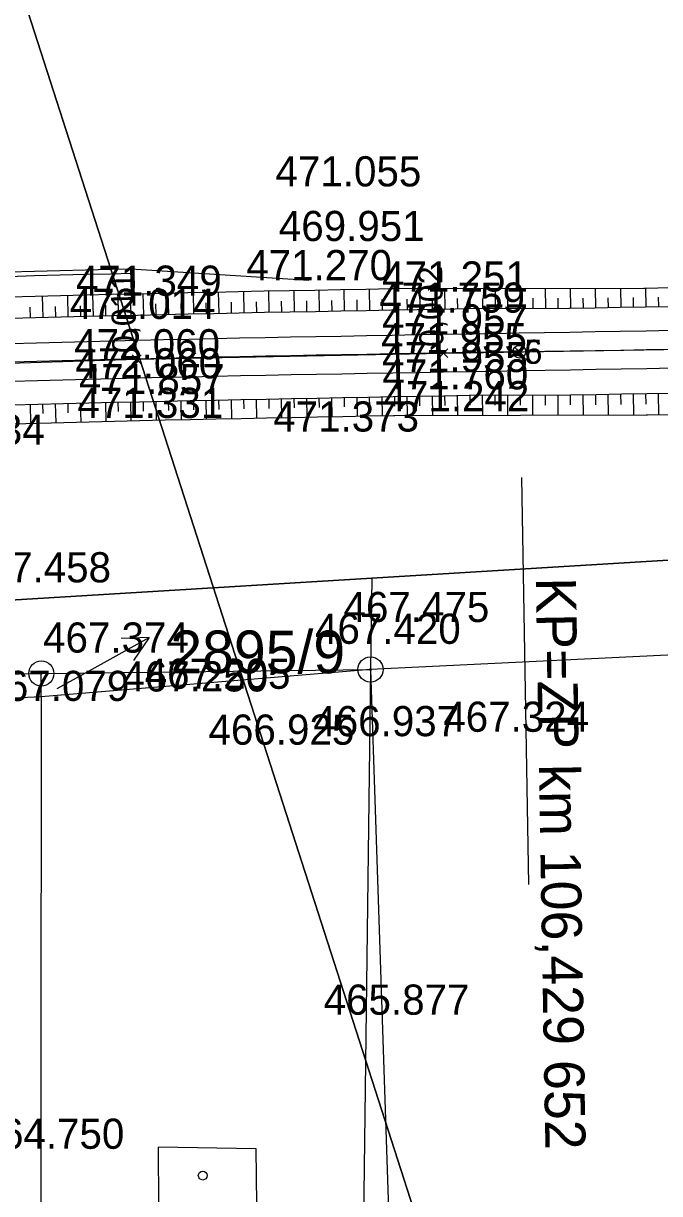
# Model space of a CAD drawing. Extents: x -758836 to -757729, y -1175316 to -1174366.
# Drawn here: x -758198.73 to -758173.42, y -1174797.31 to -1174750.75 of the extents above; entities that cross this region are included whole.
import ezdxf

# ---------------------------------------------------------------- set-up
doc = ezdxf.new("R2010")
doc.units = 0
for name, color, linetype in [('_NOR-body-stávající osa', 7, 'Continuous'), ('_NOR-návrh tenká', 7, 'Continuous'), ('_NOR-osa', 7, 'Continuous'), ('_NOR-pomocná', 7, 'Continuous'), ('_NOR-popis', 7, 'Continuous'), ('_NOR-posuny', 7, 'Continuous'), ('_NOR-svahy', 7, 'Continuous'), ('_NOR-vytyčení', 7, 'Continuous'), ('_vytyčený bod', 7, 'Continuous'), ('G_Obvod stavby', 7, 'Continuous'), ('Hranice parcel', 7, 'Continuous'), ('Parcelní čísla', 7, 'Continuous'), ('Pop  PČ popisy', 7, 'Continuous'), ('Vrstva 1', 7, 'Continuous'), ('Vrstva 61', 7, 'Continuous'), ('Značky bodu BP', 7, 'Continuous'), ('Značky budov', 7, 'Continuous')]:
    doc.layers.add(name, color=color, linetype=linetype)

# ---------------------------------------------------------------- blocks, each defined once
blk = doc.blocks.new('POINT_DISPLAY')
for p, q in [((-0.175, -0.175), (0.175, 0.175)), ((-0.175, 0.175), (0.175, -0.175))]:
    blk.add_line(p, q)

msp = doc.modelspace()

# ---------------------------------------------------------------- linework, layer by layer
at = {"layer": '_NOR-návrh tenká'}
for p, q in [((-758194.43, -1174761.512), (-758194.453, -1174760.512)), ((-758194.453, -1174760.512), (-758187.38, -1174760.969))]:
    msp.add_line(p, q, dxfattribs=at)
for points in [[(-758206.238, -1174760.86), (-758205.398, -1174760.83), (-758204.383, -1174760.794), (-758203.368, -1174760.76), (-758202.353, -1174760.727), (-758201.338, -1174760.696), (-758200.324, -1174760.665), (-758199.309, -1174760.636), (-758198.295, -1174760.608), (-758197.281, -1174760.581), (-758196.267, -1174760.556), (-758195.253, -1174760.531), (-758194.453, -1174760.512)], [(-758206.233, -1174761.04), (-758205.392, -1174761.009), (-758204.377, -1174760.974), (-758203.362, -1174760.94), (-758202.347, -1174760.907), (-758201.333, -1174760.875), (-758200.318, -1174760.845), (-758199.304, -1174760.816), (-758198.29, -1174760.788), (-758197.276, -1174760.761), (-758196.262, -1174760.736), (-758195.249, -1174760.711), (-758194.449, -1174760.692)], [(-758199.281, -1174761.636), (-758198.268, -1174761.608), (-758197.255, -1174761.581), (-758196.242, -1174761.555), (-758195.229, -1174761.53), (-758194.216, -1174761.507), (-758193.204, -1174761.483), (-758192.191, -1174761.461), (-758191.179, -1174761.44), (-758190.167, -1174761.419), (-758189.154, -1174761.398), (-758188.143, -1174761.379), (-758187.131, -1174761.36), (-758186.119, -1174761.341), (-758185.108, -1174761.322), (-758184.096, -1174761.304), (-758184.038, -1174761.303), (-758174.039, -1174761.282), (-758173.987, -1174761.281), (-758172.977, -1174761.263)], [(-758199.257, -1174762.485), (-758198.245, -1174762.458), (-758197.233, -1174762.431), (-758196.221, -1174762.405), (-758195.208, -1174762.38), (-758194.196, -1174762.356), (-758193.185, -1174762.333), (-758192.173, -1174762.311), (-758191.161, -1174762.289), (-758190.149, -1174762.269), (-758189.138, -1174762.248), (-758188.126, -1174762.229), (-758187.115, -1174762.209), (-758186.103, -1174762.191), (-758185.092, -1174762.172), (-758184.081, -1174762.154), (-758183.07, -1174762.137), (-758182.059, -1174762.119), (-758181.048, -1174762.102), (-758181.026, -1174762.101), (-758177.026, -1174762.084), (-758177.005, -1174762.083), (-758175.995, -1174762.066), (-758174.984, -1174762.048), (-758173.974, -1174762.031), (-758172.964, -1174762.013)], [(-758199.229, -1174763.485), (-758198.218, -1174763.457), (-758197.207, -1174763.43), (-758196.196, -1174763.405), (-758195.184, -1174763.38), (-758194.173, -1174763.356), (-758193.162, -1174763.333), (-758192.151, -1174763.311), (-758191.14, -1174763.289), (-758190.129, -1174763.268), (-758189.118, -1174763.248), (-758188.107, -1174763.228), (-758187.096, -1174763.209), (-758186.085, -1174763.191), (-758185.074, -1174763.172), (-758184.063, -1174763.154), (-758183.053, -1174763.137), (-758182.042, -1174763.119), (-758181.031, -1174763.102), (-758180.021, -1174763.085), (-758179.01, -1174763.067), (-758177.999, -1174763.05), (-758176.989, -1174763.033), (-758175.978, -1174763.016), (-758174.968, -1174762.998), (-758173.957, -1174762.981), (-758172.947, -1174762.963)], [(-758199.187, -1174764.985), (-758198.177, -1174764.957), (-758197.168, -1174764.93), (-758196.158, -1174764.904), (-758195.148, -1174764.879), (-758194.138, -1174764.856), (-758193.129, -1174764.833), (-758192.119, -1174764.81), (-758191.109, -1174764.789), (-758190.098, -1174764.768), (-758189.088, -1174764.748), (-758188.078, -1174764.728), (-758187.068, -1174764.709), (-758186.058, -1174764.69), (-758185.047, -1174764.672), (-758184.037, -1174764.654), (-758183.027, -1174764.636), (-758182.016, -1174764.619), (-758181.006, -1174764.602), (-758179.995, -1174764.584), (-758178.984, -1174764.567), (-758177.974, -1174764.55), (-758176.963, -1174764.533), (-758175.952, -1174764.516), (-758174.942, -1174764.498), (-758173.931, -1174764.48), (-758172.92, -1174764.462)], [(-758199.16, -1174765.934), (-758198.152, -1174765.906), (-758197.143, -1174765.88), (-758196.134, -1174765.854), (-758195.125, -1174765.829), (-758194.116, -1174765.805), (-758193.107, -1174765.782), (-758192.098, -1174765.76), (-758191.089, -1174765.739), (-758190.079, -1174765.718), (-758189.07, -1174765.698), (-758188.06, -1174765.678), (-758187.05, -1174765.659), (-758186.04, -1174765.64), (-758185.03, -1174765.622), (-758184.02, -1174765.604), (-758183.01, -1174765.586), (-758182, -1174765.569), (-758180.989, -1174765.551), (-758180.968, -1174765.551), (-758176.968, -1174765.533), (-758176.946, -1174765.533), (-758175.935, -1174765.515), (-758174.924, -1174765.498), (-758173.913, -1174765.48), (-758172.902, -1174765.462)], [(-758199.139, -1174766.684), (-758198.131, -1174766.656), (-758197.124, -1174766.629), (-758196.116, -1174766.604), (-758195.107, -1174766.579), (-758194.099, -1174766.555), (-758193.09, -1174766.532), (-758192.082, -1174766.51), (-758191.073, -1174766.488), (-758190.064, -1174766.468), (-758189.055, -1174766.447), (-758188.046, -1174766.428), (-758187.036, -1174766.409), (-758186.027, -1174766.39), (-758185.017, -1174766.372), (-758184.007, -1174766.354), (-758183.955, -1174766.353), (-758173.956, -1174766.331), (-758173.898, -1174766.33), (-758172.887, -1174766.312)]]:
    msp.add_lwpolyline(points, dxfattribs=at)
at = {"layer": '_NOR-osa'}
for points in [[(-758178.997, -1174763.817), (-758180.008, -1174763.834), (-758181.018, -1174763.852), (-758182.029, -1174763.869), (-758183.04, -1174763.886), (-758184.05, -1174763.904), (-758185.061, -1174763.922), (-758186.071, -1174763.94), (-758187.082, -1174763.959), (-758188.093, -1174763.978), (-758189.103, -1174763.998), (-758190.114, -1174764.018), (-758191.124, -1174764.039), (-758192.135, -1174764.061), (-758193.145, -1174764.083), (-758194.156, -1174764.106), (-758195.166, -1174764.13), (-758196.177, -1174764.154), (-758197.187, -1174764.18), (-758198.198, -1174764.207), (-758199.208, -1174764.235)], [(-758178.997, -1174763.817), (-758177.987, -1174763.8), (-758176.976, -1174763.783), (-758175.965, -1174763.766), (-758174.955, -1174763.748), (-758173.944, -1174763.73), (-758172.933, -1174763.712)]]:
    msp.add_lwpolyline(points, dxfattribs=at)
msp.add_circle((-758178.997, -1174763.817), 0.25, dxfattribs=at)
msp.add_circle((-758178.997, -1174763.817), 0.25, dxfattribs=at)
at = {"layer": '_NOR-pomocná'}
for points in [[(-758217.708, -1174690.839), (-758117.765, -1174658.647), (-758072.236, -1174799.995), (-758172.179, -1174832.187)], [(-758317.652, -1174723.031), (-758217.708, -1174690.839), (-758172.179, -1174832.187), (-758272.123, -1174864.38)]]:
    msp.add_lwpolyline(points, close=True, dxfattribs=at)
at = {"layer": '_NOR-popis'}
msp.add_line((-758178.912, -1174768.817), (-758178.638, -1174785.011), dxfattribs=at)
msp.add_line((-758178.912, -1174768.817), (-758178.638, -1174785.011), dxfattribs=at)
at = {"layer": '_NOR-svahy'}
for points in [[(-758197.946, -1174762.45), (-758197.969, -1174761.6)], [(-758196.946, -1174762.424), (-758196.968, -1174761.574)], [(-758195.947, -1174762.398), (-758195.968, -1174761.549)], [(-758194.947, -1174762.374), (-758194.967, -1174761.524)], [(-758193.947, -1174762.351), (-758193.967, -1174761.501)], [(-758192.948, -1174762.328), (-758192.966, -1174761.478)], [(-758191.948, -1174762.306), (-758191.966, -1174761.456)], [(-758190.948, -1174762.285), (-758190.966, -1174761.435)], [(-758189.948, -1174762.264), (-758189.965, -1174761.415)], [(-758188.948, -1174762.245), (-758188.965, -1174761.395)], [(-758187.949, -1174762.225), (-758187.965, -1174761.375)], [(-758186.949, -1174762.206), (-758186.965, -1174761.356)], [(-758185.949, -1174762.188), (-758185.964, -1174761.338)], [(-758184.949, -1174762.17), (-758184.964, -1174761.32)], [(-758183.949, -1174762.152), (-758183.964, -1174761.303)], [(-758182.949, -1174762.135), (-758182.964, -1174761.301)], [(-758181.95, -1174762.117), (-758181.964, -1174761.299)], [(-758181.45, -1174762.109), (-758181.457, -1174761.703)], [(-758180.95, -1174762.101), (-758180.953, -1174761.297)], [(-758180.45, -1174762.099), (-758180.452, -1174761.697)], [(-758179.95, -1174762.097), (-758179.953, -1174761.295)], [(-758179.45, -1174762.094), (-758179.452, -1174761.694)], [(-758178.95, -1174762.092), (-758178.953, -1174761.292)], [(-758178.45, -1174762.09), (-758178.452, -1174761.691)], [(-758177.95, -1174762.088), (-758177.953, -1174761.29)], [(-758177.45, -1174762.085), (-758177.452, -1174761.687)], [(-758176.95, -1174762.082), (-758176.963, -1174761.288)], [(-758176.45, -1174762.074), (-758176.457, -1174761.68)], [(-758175.95, -1174762.065), (-758175.963, -1174761.286)], [(-758175.45, -1174762.056), (-758175.457, -1174761.671)], [(-758174.95, -1174762.048), (-758174.963, -1174761.284)], [(-758174.45, -1174762.039), (-758174.457, -1174761.661)], [(-758173.95, -1174762.03), (-758173.964, -1174761.28)], [(-758173.45, -1174762.021), (-758173.457, -1174761.646)], [(-758198.446, -1174762.463), (-758198.458, -1174762.038)], [(-758197.446, -1174762.436), (-758197.457, -1174762.012)], [(-758196.447, -1174762.411), (-758196.457, -1174761.986)], [(-758195.447, -1174762.386), (-758195.457, -1174761.961)], [(-758194.447, -1174762.362), (-758194.457, -1174761.937)], [(-758193.447, -1174762.339), (-758193.457, -1174761.914)], [(-758192.448, -1174762.317), (-758192.457, -1174761.892)], [(-758191.448, -1174762.296), (-758191.457, -1174761.871)], [(-758190.448, -1174762.275), (-758190.457, -1174761.85)], [(-758189.448, -1174762.254), (-758189.457, -1174761.83)], [(-758188.449, -1174762.235), (-758188.457, -1174761.81)], [(-758187.449, -1174762.216), (-758187.457, -1174761.791)], [(-758186.449, -1174762.197), (-758186.457, -1174761.772)], [(-758185.449, -1174762.179), (-758185.457, -1174761.754)], [(-758184.449, -1174762.161), (-758184.457, -1174761.736)], [(-758183.449, -1174762.143), (-758183.457, -1174761.723)], [(-758182.449, -1174762.126), (-758182.457, -1174761.713)], [(-758197.468, -1174765.888), (-758197.448, -1174766.638)], [(-758196.968, -1174765.875), (-758196.959, -1174766.25)], [(-758196.469, -1174765.862), (-758196.45, -1174766.612)], [(-758195.969, -1174765.85), (-758195.96, -1174766.225)], [(-758195.469, -1174765.838), (-758195.451, -1174766.587)], [(-758194.969, -1174765.826), (-758194.96, -1174766.2)], [(-758194.469, -1174765.814), (-758194.452, -1174766.563)], [(-758193.969, -1174765.802), (-758193.961, -1174766.177)], [(-758193.469, -1174765.791), (-758193.452, -1174766.54)], [(-758192.97, -1174765.779), (-758192.961, -1174766.154)], [(-758192.47, -1174765.768), (-758192.453, -1174766.518)], [(-758191.97, -1174765.757), (-758191.962, -1174766.132)], [(-758191.47, -1174765.747), (-758191.454, -1174766.497)], [(-758190.97, -1174765.736), (-758190.962, -1174766.111)], [(-758190.47, -1174765.726), (-758190.455, -1174766.476)], [(-758189.97, -1174765.716), (-758189.963, -1174766.091)], [(-758189.47, -1174765.706), (-758189.455, -1174766.455)], [(-758188.97, -1174765.696), (-758188.963, -1174766.071)], [(-758188.471, -1174765.686), (-758188.456, -1174766.436)], [(-758187.971, -1174765.676), (-758187.964, -1174766.051)], [(-758187.471, -1174765.667), (-758187.457, -1174766.417)], [(-758186.971, -1174765.657), (-758186.964, -1174766.032)], [(-758186.471, -1174765.648), (-758186.457, -1174766.398)], [(-758185.971, -1174765.639), (-758185.964, -1174766.014)], [(-758185.471, -1174765.63), (-758185.458, -1174766.38)], [(-758184.971, -1174765.621), (-758184.965, -1174765.996)], [(-758184.471, -1174765.612), (-758184.458, -1174766.362)], [(-758183.971, -1174765.603), (-758183.965, -1174765.978)], [(-758183.471, -1174765.594), (-758183.458, -1174766.352)], [(-758182.972, -1174765.585), (-758182.965, -1174765.968)], [(-758182.472, -1174765.577), (-758182.458, -1174766.35)], [(-758181.972, -1174765.568), (-758181.965, -1174765.958)], [(-758181.472, -1174765.56), (-758181.458, -1174766.347)], [(-758180.972, -1174765.551), (-758180.965, -1174765.949)], [(-758180.472, -1174765.549), (-758180.468, -1174766.345)], [(-758179.972, -1174765.547), (-758179.97, -1174765.945)], [(-758179.472, -1174765.544), (-758179.468, -1174766.343)], [(-758178.972, -1174765.542), (-758178.97, -1174765.942)], [(-758178.472, -1174765.54), (-758178.468, -1174766.341)], [(-758177.972, -1174765.538), (-758177.97, -1174765.939)], [(-758177.472, -1174765.535), (-758177.468, -1174766.339)], [(-758176.972, -1174765.533), (-758176.97, -1174765.935)], [(-758176.472, -1174765.525), (-758176.458, -1174766.337)], [(-758175.972, -1174765.516), (-758175.965, -1174765.926)], [(-758175.472, -1174765.507), (-758175.458, -1174766.334)], [(-758174.972, -1174765.499), (-758174.965, -1174765.916)], [(-758174.472, -1174765.49), (-758174.457, -1174766.332)], [(-758173.972, -1174765.481), (-758173.965, -1174765.906)], [(-758173.472, -1174765.472), (-758173.457, -1174766.322)], [(-758198.468, -1174765.915), (-758198.447, -1174766.665)], [(-758197.968, -1174765.902), (-758197.958, -1174766.276)]]:
    msp.add_lwpolyline(points, dxfattribs=at)
at = {"layer": '_vytyčený bod'}
for q in [(-758179.097, -1174763.717), (-758179.097, -1174763.717), (-758179.097, -1174763.917), (-758179.097, -1174763.917), (-758178.897, -1174763.717), (-758178.897, -1174763.717), (-758178.897, -1174763.917), (-758178.897, -1174763.917)]:
    msp.add_line((-758178.997, -1174763.817), q, dxfattribs=at)
at = {"layer": 'G_Obvod stavby'}
msp.add_lwpolyline([(-758392.72, -1174840.756), (-758391.23, -1174838.56), (-758368.37, -1174821.64), (-758340.31, -1174807.33), (-758320.27, -1174796.89), (-758301, -1174790.21), (-758267.96, -1174782.93), (-758224.96, -1174775.27), (-758184.87, -1174772.83), (-758142.71, -1174770.26), (-758089.84, -1174768.68), (-758106.02, -1174731.44), (-758149.09, -1174725.67), (-758199.62, -1174726.6), (-758225.76, -1174732.36), (-758252.17, -1174738.18), (-758254.97, -1174739.34), (-758266.58, -1174744.16), (-758279.45, -1174749.49), (-758302.42, -1174759.02), (-758331.68, -1174770.24), (-758367.17, -1174799.81), (-758405.64, -1174832.2)], dxfattribs=at)
at = {"layer": 'Hranice parcel'}
for p, q in [((-758184.87, -1174772.83), (-758184.92, -1174776.46)), ((-758184.92, -1174776.46), (-758198.02, -1174777.55)), ((-758198.02, -1174776.62), (-758184.92, -1174776.46)), ((-758184.92, -1174776.46), (-758185.31, -1174806.74)), ((-758184.92, -1174776.46), (-758183.9, -1174806.95)), ((-758225.62, -1174776.96), (-758198.02, -1174776.62)), ((-758198.02, -1174777.55), (-758198.02, -1174776.62))]:
    msp.add_line(p, q, dxfattribs=at)
for points in [[(-757877.73, -1174631.24), (-757883.07, -1174637.8), (-757892.39, -1174640.95), (-757964.85, -1174709.42), (-757976.05, -1174741.17), (-757981.89, -1174745.86), (-757990.29, -1174747.68), (-757997.69, -1174745.08), (-758004.14, -1174738), (-758040.32, -1174755.99), (-758089.84, -1174768.68), (-758142.71, -1174770.26), (-758184.87, -1174772.83)], [(-758184.87, -1174772.83), (-758224.96, -1174775.27), (-758267.96, -1174782.93), (-758301, -1174790.21), (-758320.27, -1174796.89)], [(-758156.63, -1174775.13), (-758157.99, -1174775.16), (-758184.92, -1174776.46)], [(-758198.02, -1174777.55), (-758210.07, -1174778.13), (-758217.96, -1174778.94)], [(-758198.02, -1174777.55), (-758198.11, -1174871.18), (-758198.12, -1174878.49)], [(-758196.6, -1174797.79), (-758196.54, -1174807.31), (-758187.63, -1174807.24), (-758187.69, -1174797.73), (-758189.45, -1174797.74), (-758189.47, -1174795.54), (-758193.37, -1174795.47), (-758193.36, -1174797.77), (-758196.6, -1174797.79)]]:
    msp.add_lwpolyline(points, dxfattribs=at)
at = {"layer": 'Pop  PČ popisy'}
for p, q in [((-758196.35, -1174776.64), (-758193.725, -1174775.185)), ((-758193.725, -1174775.185), (-758194.844, -1174775.233)), ((-758193.725, -1174775.185), (-758194.358, -1174776.109)), ((-758197.39, -1174777.21), (-758196.35, -1174776.64))]:
    msp.add_line(p, q, dxfattribs=at)
at = {"layer": 'Vrstva 1'}
msp.add_lwpolyline([(-758275.047, -1174773.289), (-758265.484, -1174771.118), (-758253.61, -1174768.888), (-758243.69, -1174767.426), (-758231.371, -1174766.042), (-758219.363, -1174765.122), (-758206.915, -1174764.505), (-758194.225, -1174764.118), (-758182.013, -1174763.871), (-758170.862, -1174763.683), (-758162.019, -1174763.496), (-758153.195, -1174763.228), (-758152.069, -1174763.19), (-758141.836, -1174762.716), (-758130.402, -1174761.933), (-758120.726, -1174760.981), (-758108.612, -1174759.398), (-758096.467, -1174757.277), (-758085.591, -1174754.917)], dxfattribs=at)
at = {"layer": 'Značky bodu BP'}
for centre, radius in [((-758198.02, -1174776.62), 0.5), ((-758184.92, -1174776.46), 0.5), ((-758198.02, -1174776.62), 0.0303), ((-758184.92, -1174776.46), 0.0303)]:
    msp.add_circle(centre, radius, dxfattribs=at)
at = {"layer": 'Značky budov'}
msp.add_circle((-758191.597, -1174796.599), 0.175, dxfattribs=at)

# ---------------------------------------------------------------- block references
at = {"layer": '_NOR-body-stávající osa'}
for p in [(-758194.225, -1174764.118), (-758182.013, -1174763.871)]:
    msp.add_blockref('POINT_DISPLAY', p, dxfattribs=at)
at = {"layer": '_NOR-vytyčení'}
msp.add_blockref('POINT_DISPLAY', (-758178.997, -1174763.817), dxfattribs=at)
msp.add_blockref('POINT_DISPLAY', (-758178.997, -1174763.817), dxfattribs=at)

# ---------------------------------------------------------------- texts
at = {"layer": '_NOR-popis'}
msp.add_text('KP=ZP km 106,429 652', height=1.59987, rotation=270.9709, dxfattribs=at).set_placement((-758178.345, -1174772.808))
msp.add_text('KP=ZP km 106,429 652', height=1.59987, rotation=270.9709, dxfattribs=at).set_placement((-758178.345, -1174772.808))
at = {"layer": '_NOR-posuny'}
for s, rotation, p in [('0,011', 91.354, (-758194.231, -1174763.858)), ('0,002', 90.981, (-758182.017, -1174763.619))]:
    msp.add_text(s, height=0.9599, rotation=rotation, dxfattribs=at).set_placement(p)
at = {"layer": '_vytyčený bod'}
for s in ['5', '5', '6', '6']:
    msp.add_text(s, height=0.96, dxfattribs=at).set_placement((-758178.797, -1174764.297))
at = {"layer": 'Parcelní čísla'}
msp.add_text('2895/9', height=1.7, dxfattribs=at).set_placement((-758192.885, -1174776.61))
at = {"layer": 'Vrstva 61'}
for s, p in [('471.055', (-758188.7, -1174757.238)), ('469.951', (-758188.568, -1174759.412)), ('471.270', (-758189.865, -1174760.969)), ('471.251', (-758184.458, -1174761.421)), ('471.349', (-758196.641, -1174761.588)), ('471.759', (-758184.572, -1174762.262)), ('472.014', (-758196.891, -1174762.512)), ('471.957', (-758184.458, -1174763.13)), ('472.060', (-758196.71, -1174764.118)), ('471.955', (-758184.498, -1174763.871)), ('471.955', (-758184.46, -1174764.626)), ('472.060', (-758196.664, -1174764.875)), ('471.857', (-758196.524, -1174765.501)), ('471.760', (-758184.444, -1174765.316)), ('471.242', (-758184.401, -1174766.183)), ('471.331', (-758196.583, -1174766.451)), ('471.373', (-758188.791, -1174766.992)), ('471.734', (-758203.686, -1174767.514)), ('467.458', (-758201.047, -1174772.993)), ('467.475', (-758185.994, -1174774.572)), ('467.420', (-758187.13, -1174775.44)), ('467.374', (-758197.949, -1174775.788)), ('467.250', (-758194.795, -1174777.335)), ('467.205', (-758193.908, -1174777.229)), ('467.079', (-758200.321, -1174777.712)), ('466.937', (-758187.196, -1174779.114)), ('467.324', (-758182.025, -1174778.939)), ('466.925', (-758191.366, -1174779.452)), ('465.877', (-758186.784, -1174790.197)), ('464.750', (-758200.517, -1174795.532))]:
    msp.add_text(s, height=1.2, dxfattribs=at).set_placement(p)

doc.saveas('drawing.dxf')
